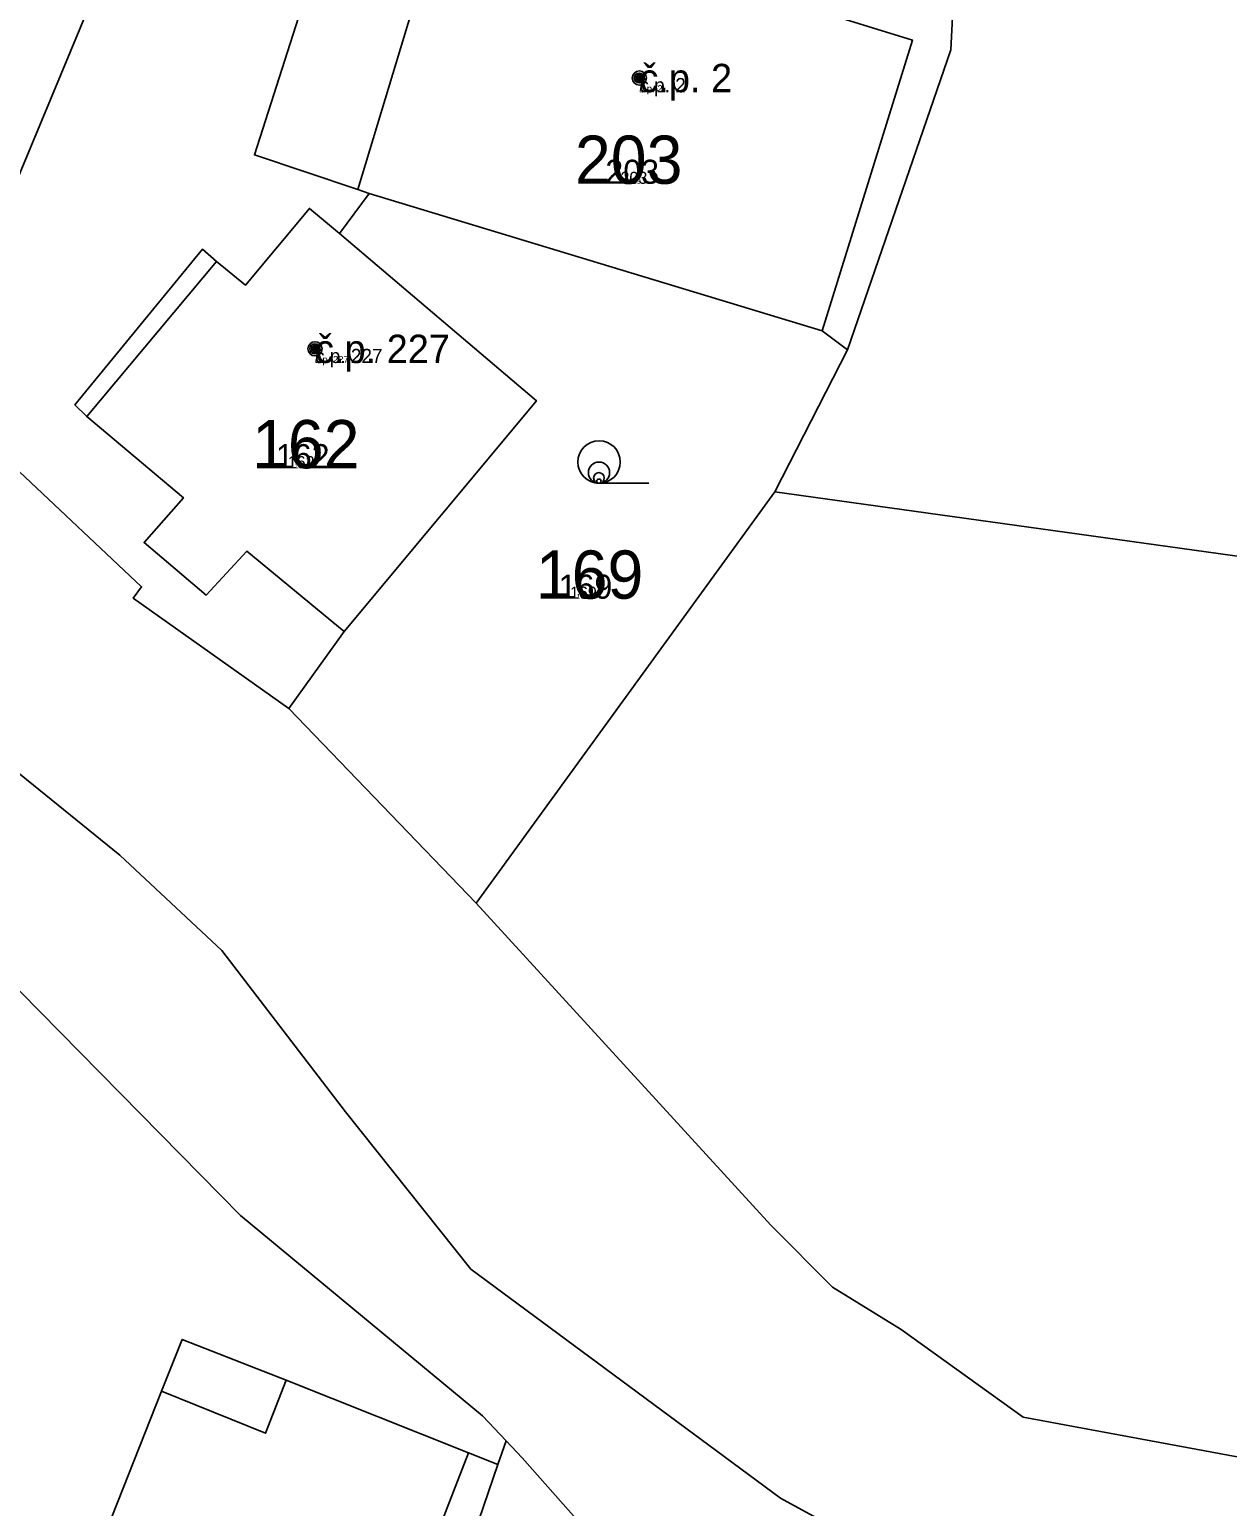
# Model space of a CAD drawing. Extents: x -744652 to -739090, y -980828 to -975855.
# Drawn here: x -742360.9 to -742318.6, y -978772.2 to -978720.1 of the extents above; entities that cross this region are included whole.
import ezdxf

# ---------------------------------------------------------------- set-up
doc = ezdxf.new("R2010")
doc.units = 0
for name, color, linetype in [('KAT_02_hranice parcel', 7, 'Continuous'), ('KAT_03_1000_st čísla parcelní', 7, 'Continuous'), ('KAT_03_1000_čísla parcelní', 7, 'Continuous'), ('KAT_03_1000_čísla popisná', 7, 'Continuous'), ('KAT_03_100_st čísla parcelní', 7, 'Continuous'), ('KAT_03_100_čísla parcelní', 7, 'Continuous'), ('KAT_03_100_čísla popisná', 7, 'Continuous'), ('KAT_03_250_st čísla parcelní', 7, 'Continuous'), ('KAT_03_250_čísla parcelní', 7, 'Continuous'), ('KAT_03_250_čísla popisná', 7, 'Continuous'), ('KAT_03_500_st čísla parcelní', 7, 'Continuous'), ('KAT_03_500_čísla parcelní', 7, 'Continuous'), ('KAT_03_500_čísla popisná', 7, 'Continuous'), ('KAT_04_vnitřní kresba', 7, 'Continuous'), ('KAT_05_1000_značky kultur', 7, 'Continuous'), ('KAT_05_100_značky kultur', 7, 'Continuous'), ('KAT_05_250_značky kultur', 7, 'Continuous'), ('KAT_05_500_značky kultur', 7, 'Continuous'), ('KAT_07_1000_značky budov', 7, 'Continuous'), ('KAT_07_100_značky budov', 7, 'Continuous'), ('KAT_07_500_značky budov', 7, 'Continuous'), ('KAT_14_plocha_budovy', 7, 'Continuous')]:
    doc.layers.add(name, color=color, linetype=linetype)

msp = doc.modelspace()

# ---------------------------------------------------------------- linework, layer by layer
at = {"layer": 'KAT_02_hranice parcel'}
for p, q in [((-742348.9, -978725.89), (-742349.95, -978727.3)), ((-742349.3, -978725.75), (-742348.9, -978725.89)), ((-742348.9, -978725.89), (-742332.92, -978730.74)), ((-742332.03, -978731.41), (-742332.92, -978730.74)), ((-742334.59, -978736.41), (-742332.03, -978731.41)), ((-742345.13, -978750.92), (-742334.59, -978736.41)), ((-742349.78, -978741.34), (-742351.74, -978744.05)), ((-742351.74, -978744.05), (-742345.13, -978750.92)), ((-742344.07, -978769.87), (-742344.36, -978770.71))]:
    msp.add_line(p, q, dxfattribs=at)
for points in [[(-742404.92, -978706.02), (-742392.32, -978728.98), (-742392, -978729.6), (-742391.29, -978729.29), (-742388.01, -978732.29), (-742388.05, -978731.92), (-742366.82, -978734.5), (-742362.9, -978735.46), (-742361.94, -978735.42), (-742361.36, -978735.86), (-742361.25, -978735.7), (-742356.93, -978739.76), (-742357.22, -978740.16), (-742351.74, -978744.05)], [(-742349.3, -978725.75), (-742352.95, -978724.53), (-742347.7, -978708.15), (-742346.68, -978708.52)], [(-742327.81, -978709.51), (-742328.39, -978720.82), (-742332.03, -978731.41)], [(-742372.31, -978727.27), (-742363.62, -978730.92), (-742356.99, -978714.98)], [(-742332.92, -978730.74), (-742329.74, -978720.48), (-742346.17, -978715.41), (-742349.3, -978725.75)], [(-742334.59, -978736.41), (-742300.11, -978741.21), (-742298.45, -978722.62)], [(-742349.95, -978727.3), (-742351.01, -978726.42), (-742353.26, -978729.12), (-742354.29, -978728.29), (-742354.78, -978727.86), (-742359.28, -978733.34), (-742358.86, -978733.76), (-742355.45, -978736.62), (-742356.84, -978738.2), (-742354.65, -978740.05), (-742353.21, -978738.5), (-742349.78, -978741.34)], [(-742349.78, -978741.34), (-742343, -978733.2), (-742349.95, -978727.3)], [(-742330.54, -978774), (-742334.39, -978771.9), (-742345.32, -978763.82), (-742349.74, -978758.28), (-742354.1, -978752.58), (-742357.7, -978749.22), (-742362.74, -978745.15), (-742365.99, -978743.11), (-742367.63, -978742.38), (-742369.86, -978741.8), (-742374.48, -978740.78), (-742385.3, -978739.17), (-742387.66, -978738.72), (-742391.01, -978738.29), (-742392.15, -978737.92), (-742393.45, -978737.07), (-742394.26, -978735.9), (-742394.44, -978735.76), (-742397.84, -978731.74), (-742399.17, -978731.4)], [(-742345.13, -978750.92), (-742334.74, -978762.27), (-742332.56, -978764.46), (-742330.14, -978765.95), (-742325.83, -978769.04), (-742310.11, -978771.96), (-742285.79, -978771.27), (-742283.91, -978768.56)], [(-742361.91, -978753.32), (-742353.44, -978761.93), (-742344.9, -978768.99), (-742344.07, -978769.87)], [(-742344.36, -978770.71), (-742345.4, -978770.3), (-742351.83, -978767.74), (-742355.5, -978766.3), (-742356.22, -978768.12), (-742360.3, -978778.45), (-742355.83, -978780.31), (-742357.64, -978785.07), (-742350.84, -978784.79), (-742350.47, -978783.75), (-742348.79, -978784.19)], [(-742331.84, -978777.5), (-742341.25, -978773.03), (-742343.51, -978770.48), (-742344.07, -978769.87)], [(-742348.34, -978782.36), (-742345.03, -978772.67), (-742344.36, -978770.71)]]:
    msp.add_lwpolyline(points, dxfattribs=at)
at = {"layer": 'KAT_03_1000_čísla popisná'}
for centre in [(-742339.37, -978721.82), (-742339.37, -978721.82), (-742350.81, -978731.37), (-742350.81, -978731.37)]:
    msp.add_circle(centre, 0.25, dxfattribs=at)
at = {"layer": 'KAT_03_100_čísla popisná'}
for centre in [(-742339.37, -978721.82), (-742339.37, -978721.82), (-742350.81, -978731.37), (-742350.81, -978731.37)]:
    msp.add_circle(centre, 0.025, dxfattribs=at)
at = {"layer": 'KAT_03_250_čísla popisná'}
for centre in [(-742339.37, -978721.82), (-742339.37, -978721.82), (-742350.81, -978731.37), (-742350.81, -978731.37)]:
    msp.add_circle(centre, 0.0625, dxfattribs=at)
at = {"layer": 'KAT_03_500_čísla popisná'}
for centre in [(-742339.37, -978721.82), (-742339.37, -978721.82), (-742350.81, -978731.37), (-742350.81, -978731.37)]:
    msp.add_circle(centre, 0.125, dxfattribs=at)
at = {"layer": 'KAT_04_vnitřní kresba'}
for p, q in [((-742358.86, -978733.76), (-742354.29, -978728.29)), ((-742356.22, -978768.12), (-742352.56, -978769.61)), ((-742352.56, -978769.61), (-742351.83, -978767.74)), ((-742346.15, -978772.24), (-742345.4, -978770.3))]:
    msp.add_line(p, q, dxfattribs=at)
at = {"layer": 'KAT_05_1000_značky kultur'}
msp.add_line((-742340.793, -978736.11), (-742339.043, -978736.11), dxfattribs=at)
msp.add_circle((-742340.793, -978735.36), 0.75, dxfattribs=at)
at = {"layer": 'KAT_05_100_značky kultur'}
msp.add_line((-742340.799, -978736.11), (-742340.624, -978736.11), dxfattribs=at)
msp.add_circle((-742340.799, -978736.035), 0.075, dxfattribs=at)
at = {"layer": 'KAT_05_250_značky kultur'}
msp.add_line((-742340.798, -978736.11), (-742340.361, -978736.11), dxfattribs=at)
msp.add_circle((-742340.798, -978735.922), 0.187, dxfattribs=at)
at = {"layer": 'KAT_05_500_značky kultur'}
msp.add_line((-742340.797, -978736.11), (-742339.922, -978736.11), dxfattribs=at)
msp.add_circle((-742340.796, -978735.735), 0.375, dxfattribs=at)
at = {"layer": 'KAT_07_1000_značky budov'}
for centre in [(-742339.377, -978721.819), (-742350.817, -978731.369)]:
    msp.add_circle(centre, 0.175, dxfattribs=at)
at = {"layer": 'KAT_07_100_značky budov'}
for centre in [(-742339.371, -978721.82), (-742350.811, -978731.37)]:
    msp.add_circle(centre, 0.0175, dxfattribs=at)
at = {"layer": 'KAT_07_500_značky budov'}
for centre, radius in [((-742339.373, -978721.82), 0.0875), ((-742339.372, -978721.82), 0.0438), ((-742350.813, -978731.37), 0.0875), ((-742350.812, -978731.37), 0.0438)]:
    msp.add_circle(centre, radius, dxfattribs=at)
at = {"layer": 'KAT_14_plocha_budovy'}
for points in [[(-742349.3, -978725.75), (-742348.9, -978725.89), (-742332.92, -978730.74), (-742329.74, -978720.48), (-742346.17, -978715.41)], [(-742354.29, -978728.29), (-742358.86, -978733.76), (-742355.45, -978736.62), (-742356.84, -978738.2), (-742354.65, -978740.05), (-742353.21, -978738.5), (-742349.78, -978741.34), (-742343, -978733.2), (-742349.95, -978727.3), (-742351.01, -978726.42), (-742353.26, -978729.12)], [(-742356.22, -978768.12), (-742360.3, -978778.45), (-742355.83, -978780.31), (-742350.16, -978782.66), (-742346.15, -978772.24), (-742345.4, -978770.3), (-742351.83, -978767.74), (-742352.56, -978769.61)]]:
    msp.add_lwpolyline(points, close=True, dxfattribs=at)

# ---------------------------------------------------------------- texts
at = {"layer": 'KAT_03_1000_st čísla parcelní'}
for s, p in [('203', (-742341.644, -978725.55)), ('162', (-742353.034, -978735.58))]:
    msp.add_text(s, height=1.7, dxfattribs=at).set_placement(p)
at = {"layer": 'KAT_03_1000_čísla parcelní'}
msp.add_text('169', height=1.7, dxfattribs=at).set_placement((-742343.024, -978740.18))
at = {"layer": 'KAT_03_1000_čísla popisná'}
for s, height, p in [('č.p. 2', 1, (-742339.37, -978722.32)), ('203', 0.017, (-742339.524, -978725.55)), ('č.p. 227', 1, (-742350.81, -978731.87)), ('162', 0.017, (-742351.371, -978735.58))]:
    msp.add_text(s, height=height, dxfattribs=at).set_placement(p)
at = {"layer": 'KAT_03_100_st čísla parcelní'}
for s, p in [('203', (-742339.717, -978725.55)), ('162', (-742351.522, -978735.58))]:
    msp.add_text(s, height=0.17, dxfattribs=at).set_placement(p)
at = {"layer": 'KAT_03_100_čísla parcelní'}
msp.add_text('169', height=0.17, dxfattribs=at).set_placement((-742341.579, -978740.18))
at = {"layer": 'KAT_03_100_čísla popisná'}
for s, height, p in [('č.p. 2', 0.1, (-742339.37, -978722.32)), ('203', 0.0017, (-742339.505, -978725.55)), ('č.p. 227', 0.1, (-742350.81, -978731.87)), ('162', 0.0017, (-742351.356, -978735.58))]:
    msp.add_text(s, height=height, dxfattribs=at).set_placement(p)
at = {"layer": 'KAT_03_250_st čísla parcelní'}
for s, p in [('203', (-742340.038, -978725.55)), ('162', (-742351.774, -978735.58))]:
    msp.add_text(s, height=0.425, dxfattribs=at).set_placement(p)
at = {"layer": 'KAT_03_250_čísla parcelní'}
msp.add_text('169', height=0.425, dxfattribs=at).set_placement((-742341.819, -978740.18))
at = {"layer": 'KAT_03_250_čísla popisná'}
for s, height, p in [('č.p. 2', 0.25, (-742339.37, -978722.32)), ('203', 0.00425, (-742339.508, -978725.55)), ('č.p. 227', 0.25, (-742350.81, -978731.87)), ('162', 0.00425, (-742351.358, -978735.58))]:
    msp.add_text(s, height=height, dxfattribs=at).set_placement(p)
at = {"layer": 'KAT_03_500_st čísla parcelní'}
for s, p in [('203', (-742340.573, -978725.55)), ('162', (-742352.194, -978735.58))]:
    msp.add_text(s, height=0.85, dxfattribs=at).set_placement(p)
at = {"layer": 'KAT_03_500_čísla parcelní'}
msp.add_text('169', height=0.85, dxfattribs=at).set_placement((-742342.221, -978740.18))
at = {"layer": 'KAT_03_500_čísla popisná'}
for s, height, p in [('č.p. 2', 0.5, (-742339.37, -978722.32)), ('203', 0.0085, (-742339.513, -978725.55)), ('č.p. 227', 0.5, (-742350.81, -978731.87)), ('162', 0.0085, (-742351.363, -978735.58))]:
    msp.add_text(s, height=height, dxfattribs=at).set_placement(p)

doc.saveas('drawing.dxf')
